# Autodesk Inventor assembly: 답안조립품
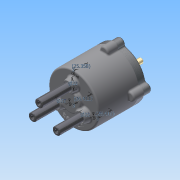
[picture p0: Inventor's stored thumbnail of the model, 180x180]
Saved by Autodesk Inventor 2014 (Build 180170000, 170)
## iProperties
Created: 2015-09
Part Number: 답안조립품
Document SubType Name: Assembly
Designer: study
Mass: 2160.05 g
Surface Area: 1801.16 cm^2
Volume: 438.498 cm^3
Density: 4.92603 g/cm^3
Author: study
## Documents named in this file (14)
- C:\Users\study\Desktop\350916V1009\답안조립품.iam
- C:\Users\study\Desktop\350916V1009\몸체.ipt
- C:\Users\study\Desktop\350916V1009\메인 축.ipt
- C:\Users\study\Desktop\350916V1009\슬라이드 축.ipt
- C:\Users\study\Desktop\350916V1009\판캠.ipt
- C:\Users\study\Desktop\350916V1009\멈춤링 22 x 1.2.ipt
- C:\Users\study\Desktop\350916V1009\멈춤링 10 x 1.ipt
- C:\Users\study\Desktop\350916V1009\베어링 NA 4900.ipt
- C:\Users\study\Desktop\350916V1009\M5x0.8x20.ipt
- C:\Users\study\Desktop\350916V1009\오일실.ipt
- C:\Users\study\Desktop\350916V1009\커버.ipt
- C:\Users\study\Desktop\350916V1009\11-가변 스프링.ipt
- C:\Users\study\Desktop\350916V1009\12-가변 스프링.ipt
- C:\Users\study\Desktop\350916V1009\13-가변 스프링.ipt
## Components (7 placed, 4 different names)
1. 11-가변 스프링:1
2. 12-가변 스프링:1
3. 13-가변 스프링:1
4. M5x0.8x20:1
5. M5x0.8x20:2
6. M5x0.8x20:3
7. M5x0.8x20:4
